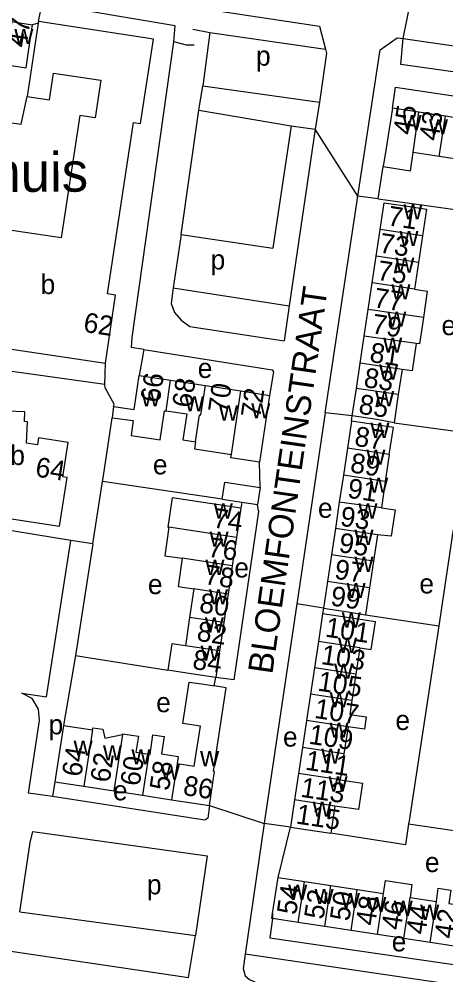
# Model space of a CAD drawing. Extents: x 163012 to 165277, y 382513 to 383987.
# Drawn here: x 163502.4 to 163589, y 383224 to 383417.8 of the extents above; entities that cross this region are included whole.
import ezdxf

# ---------------------------------------------------------------- set-up
doc = ezdxf.new("R2010")
doc.units = 0
for name, color, linetype in [('BLT_Basislijn', 7, 'Continuous'), ('BLT_Bebouwing', 7, 'Continuous'), ('BLT_Bebouwing_beschrifting', 7, 'Continuous'), ('BLT_Centroide', 7, 'Continuous'), ('BLT_Huisnummer', 7, 'Continuous'), ('BLT_Huisnummer_ tussenligend', 7, 'Continuous'), ('BLT_Onderverdeling_panden', 7, 'Continuous'), ('BLT_Straatnaam', 7, 'Continuous'), ('BLT_Vlakafsluiter', 7, 'Continuous')]:
    doc.layers.add(name, color=color, linetype=linetype)

msp = doc.modelspace()

# ---------------------------------------------------------------- linework, layer by layer
at = {"layer": 'BLT_Basislijn'}
for p, q in [((163506.38, 383417.32), (163507.11, 383420.98)), ((163506.33, 383417.01), (163505.14, 383416.66)), ((163537.69, 383415.82), (163541.14, 383415.15)), ((163541.14, 383415.15), (163539.72, 383404.32)), ((163580.33, 383413.88), (163605.73, 383410.21)), ((163538.92, 383399.38), (163539.72, 383404.32)), ((163539.72, 383404.32), (163563.35, 383400.97)), ((163535.3, 383374.17), (163538.92, 383399.38)), ((163538.92, 383399.38), (163557.66, 383396.21)), ((163563.35, 383400.97), (163562.49, 383395.52)), ((163557.66, 383396.21), (163553.89, 383371.35)), ((163557.66, 383396.21), (163562.49, 383395.52)), ((163575.3, 383381.36), (163576.31, 383387.91)), ((163564.55, 383337.96), (163571.19, 383381.89)), ((163575.3, 383381.36), (163571.19, 383381.89)), ((163533.7, 383363.31), (163557.22, 383359.7)), ((163527.73, 383350.8), (163526.81, 383345.53)), ((163519.82, 383343.69), (163485.89, 383348.51)), ((163519.82, 383343.69), (163519.94, 383348.06)), ((163570.03, 383337.36), (163564.55, 383337.96)), ((163569.85, 383336.26), (163570.03, 383337.36)), ((163578.51, 383335.96), (163593.55, 383333.89)), ((163551.34, 383322.82), (163551.22, 383328)), ((163517.38, 383311.39), (163519.36, 383324.07)), ((163543.64, 383320.43), (163519.36, 383324.07)), ((163547.62, 383319.84), (163547.43, 383318.62)), ((163550.99, 383318.07), (163551.02, 383317.97)), ((163512.92, 383312.11), (163497.29, 383314.66)), ((163590.52, 383314.29), (163587.56, 383294.8)), ((163508, 383280.37), (163512.92, 383312.11)), ((163517.38, 383311.39), (163512.92, 383312.11)), ((163517.38, 383311.39), (163513.9, 383288.76)), ((163564.18, 383298.34), (163558.8, 383299.24)), ((163564.18, 383298.34), (163564.02, 383297.21)), ((163572.72, 383297.03), (163587.56, 383294.8)), ((163513.9, 383288.76), (163511.42, 383274.58)), ((163513.9, 383288.76), (163532.64, 383285.77)), ((163542.02, 383282.58), (163542.32, 383284.32)), ((163502.99, 383281.11), (163508, 383280.37)), ((163509.68, 383263.14), (163509.22, 383260.12)), ((163509.22, 383260.12), (163504.38, 383260.8)), ((163557.47, 383253.93), (163552.15, 383254.66)), ((163554.99, 383243.74), (163557.47, 383253.93)), ((163581.46, 383254.63), (163597.96, 383252.2)), ((163502.59, 383236.74), (163538.23, 383231.93)), ((163553.88, 383236.45), (163553.82, 383235.38)), ((163463.3, 383234.3), (163536.83, 383223.46)), ((163536.83, 383223.46), (163538.23, 383231.93))]:
    msp.add_line(p, q, dxfattribs=at)
for points in [[(163389.35, 383444), (163390.61, 383444.5), (163392.76, 383444.65), (163405.07, 383441.7), (163432.57, 383436.22), (163489.01, 383427.6), (163533.29, 383420.96), (163563.38, 383416.41), (163564.62, 383411.74)], [(163533.82, 383413.21), (163534.13, 383416.47), (163507.11, 383420.98)], [(163541.14, 383415.15), (163564.62, 383411.74)], [(163527.73, 383350.8), (163525.21, 383351.24), (163525.36, 383353.23), (163533.82, 383413.21)], [(163537.98, 383412.53), (163536.41, 383412.53), (163533.82, 383413.21)], [(163571.19, 383381.89), (163575.68, 383411.58), (163579.12, 383414.03), (163580.33, 383413.88)], [(163605.73, 383410.21), (163604.9, 383405.14), (163579.87, 383408.64), (163580.33, 383413.88)], [(163564.62, 383411.74), (163564.81, 383410.91), (163563.35, 383400.97)], [(163578.16, 383399.8), (163578.81, 383404.02), (163627.18, 383396.81)], [(163483.5, 383399.29), (163502.86, 383396.53), (163504.09, 383402.15)], [(163562.49, 383395.52), (163557.22, 383359.7)], [(163575.3, 383381.36), (163585.09, 383380), (163600.04, 383377.94), (163599.84, 383373.27)], [(163535.3, 383374.17), (163533.7, 383363.31)], [(163535.3, 383374.17), (163553.89, 383371.35)], [(163533.7, 383363.31), (163533.27, 383360.13), (163533.95, 383358.32), (163535.29, 383356.79), (163537.09, 383355.49), (163556.19, 383352.61)], [(163557.22, 383359.7), (163556.19, 383352.61)], [(163527.73, 383350.8), (163553.77, 383346.71), (163554.08, 383346.29), (163553.26, 383341.52)], [(163521.58, 383339.27), (163521.71, 383339.74), (163519.91, 383343.02), (163519.82, 383343.69)], [(163564.55, 383337.96), (163558.86, 383299.64), (163558.8, 383299.24)], [(163519.36, 383324.07), (163519.54, 383325.21), (163521.29, 383336.99)], [(163551.02, 383317.97), (163546.03, 383283.81), (163542.32, 383284.32)], [(163550.99, 383318.07), (163550.82, 383319.37)], [(163558.8, 383299.24), (163552.24, 383255.24), (163552.15, 383254.66)], [(163587.56, 383294.8), (163581.55, 383255.2), (163581.46, 383254.63)], [(163504.38, 383260.8), (163506.6, 383275.54), (163506.36, 383277.84), (163505.1, 383280.02), (163502.99, 383281.11)], [(163541.05, 383258.31), (163540.72, 383255.76), (163540.14, 383255.38), (163509.22, 383260.12)], [(163552.15, 383254.66), (163548.32, 383228.18)], [(163581.46, 383254.63), (163580.8, 383250.37), (163565.65, 383252.71)], [(163502.59, 383236.74), (163504.67, 383250.85), (163505.24, 383253.04), (163540.6, 383248.13), (163538.23, 383231.93)], [(163553.82, 383235.38), (163553.31, 383231.45), (163601.31, 383224.5)], [(163548.32, 383228.18), (163547.89, 383225.23), (163548.33, 383223.8), (163549.18, 383223.01), (163550.64, 383222.36), (163551.73, 383222.16)], [(163600.65, 383220.44), (163548.32, 383228.18)]]:
    msp.add_lwpolyline(points, dxfattribs=at)
at = {"layer": 'BLT_Bebouwing'}
for p, q in [((163499.13, 383417.6), (163505.14, 383416.66)), ((163506.33, 383417.01), (163504.09, 383402.15)), ((163506.38, 383417.32), (163506.33, 383417.01)), ((163578.16, 383399.8), (163576.89, 383391.63)), ((163583.54, 383398.97), (163578.16, 383399.8)), ((163588.91, 383398.13), (163583.54, 383398.97)), ((163594.29, 383397.3), (163588.91, 383398.13)), ((163576.89, 383391.63), (163576.31, 383387.91)), ((163587.64, 383389.97), (163582.4, 383390.78)), ((163593.02, 383389.13), (163587.64, 383389.97)), ((163574.9, 383369.75), (163575.71, 383375.17)), ((163584.28, 383373.87), (163583.46, 383368.45)), ((163574.09, 383364.33), (163574.9, 383369.75)), ((163583.46, 383368.45), (163582.65, 383363.03)), ((163573.27, 383358.92), (163574.09, 383364.33)), ((163572.46, 383353.5), (163573.27, 383358.92)), ((163571.64, 383348.08), (163572.46, 383353.5)), ((163570.87, 383342.94), (163571.64, 383348.08)), ((163526.81, 383345.53), (163533.17, 383344.59)), ((163580.14, 383346.79), (163579.36, 383341.66)), ((163533.17, 383344.59), (163540.25, 383343.54)), ((163540.25, 383343.54), (163547.42, 383342.41)), ((163547.42, 383342.41), (163553.26, 383341.52)), ((163553.26, 383341.52), (163551.22, 383328)), ((163570.03, 383337.36), (163570.87, 383342.94)), ((163579.36, 383341.66), (163578.51, 383335.96)), ((163521.58, 383339.27), (163521.29, 383336.99)), ((163569.85, 383336.26), (163569.04, 383330.8)), ((163569.04, 383330.8), (163568.22, 383325.34)), ((163577.54, 383329.52), (163576.72, 383324.06)), ((163543.64, 383320.43), (163544.15, 383323.9)), ((163544.15, 383323.9), (163551.34, 383322.82)), ((163568.22, 383325.34), (163567.4, 383319.86)), ((163551.34, 383322.82), (163550.82, 383319.37)), ((163543.64, 383320.43), (163547.62, 383319.84)), ((163547.62, 383319.84), (163550.82, 383319.37)), ((163567.4, 383319.86), (163566.6, 383314.51)), ((163547.43, 383318.62), (163546.54, 383312.7)), ((163566.6, 383314.51), (163565.8, 383309.15)), ((163546.54, 383312.7), (163545.68, 383306.95)), ((163575.12, 383313.23), (163574.32, 383307.87)), ((163565.8, 383309.15), (163565, 383303.79)), ((163545.68, 383306.95), (163544.82, 383301.2)), ((163565, 383303.79), (163564.18, 383298.34)), ((163573.54, 383302.5), (163572.72, 383297.03)), ((163537.89, 383302.24), (163537.03, 383296.49)), ((163544.82, 383301.2), (163543.96, 383295.45)), ((163564.02, 383297.21), (163563.17, 383291.59)), ((163537.03, 383296.49), (163536.17, 383290.74)), ((163543.96, 383295.45), (163543.09, 383289.7)), ((163563.17, 383291.59), (163562.36, 383286.25)), ((163543.09, 383289.7), (163542.32, 383284.32)), ((163562.36, 383286.25), (163561.55, 383280.91)), ((163561.55, 383280.91), (163560.75, 383275.57)), ((163560.75, 383275.57), (163559.92, 383270.09)), ((163511.42, 383274.58), (163509.68, 383263.14)), ((163511.42, 383274.58), (163517.33, 383273.68)), ((163569.17, 383274.3), (163568.35, 383268.83)), ((163559.92, 383270.09), (163559.12, 383264.79)), ((163568.35, 383268.83), (163567.55, 383263.52)), ((163559.12, 383264.79), (163558.31, 383259.45)), ((163509.68, 383263.14), (163515.55, 383262.24)), ((163515.55, 383262.24), (163521.63, 383261.3)), ((163521.63, 383261.3), (163527.5, 383260.4)), ((163527.5, 383260.4), (163533.36, 383259.49)), ((163533.36, 383259.49), (163541.05, 383258.31)), ((163558.31, 383259.45), (163557.47, 383253.93)), ((163566.48, 383258.22), (163565.65, 383252.71)), ((163553.88, 383236.45), (163554.99, 383243.74)), ((163560.33, 383242.92), (163565.68, 383242.1)), ((163565.68, 383242.1), (163571.03, 383241.28)), ((163571.03, 383241.28), (163576.39, 383240.46)), ((163581.74, 383239.65), (163587.09, 383238.83)), ((163559.07, 383234.59), (163553.82, 383235.38)), ((163564.43, 383233.78), (163559.07, 383234.59)), ((163569.78, 383232.98), (163564.43, 383233.78)), ((163575.14, 383232.17), (163569.78, 383232.98)), ((163580.49, 383231.36), (163575.14, 383232.17)), ((163585.85, 383230.56), (163580.49, 383231.36)), ((163591.2, 383229.75), (163585.85, 383230.56))]:
    msp.add_line(p, q, dxfattribs=at)
for points in [[(163525.64, 383396.87), (163527.04, 383396.66), (163529.73, 383413.79), (163506.38, 383417.32)], [(163497.81, 383408.88), (163500, 383408.56), (163503.86, 383407.96), (163504.41, 383411.71), (163505.14, 383416.66)], [(163504.09, 383402.15), (163508.6, 383401.47), (163509.42, 383406.9), (163519.01, 383405.45), (163517.86, 383397.82)], [(163517.86, 383397.82), (163514.74, 383398.29), (163510.97, 383373.47)], [(163519.94, 383348.06), (163522.02, 383361.83), (163520.38, 383362.08), (163525.64, 383396.87)], [(163576.31, 383387.91), (163581.82, 383387.05), (163582.4, 383390.78)], [(163575.71, 383375.17), (163576.52, 383380.57), (163581.21, 383379.87), (163585.09, 383379.28), (163584.28, 383373.87)], [(163510.97, 383373.47), (163500, 383375.11), (163498.62, 383364.57), (163484.68, 383366.66), (163483.87, 383361.24), (163486.59, 383360.83)], [(163582.65, 383363.03), (163585.25, 383362.62), (163584.45, 383357.28)], [(163486.59, 383360.83), (163485.45, 383353.23), (163500, 383351.03), (163519.94, 383348.06)], [(163584.45, 383357.28), (163583.64, 383351.94), (163583, 383352.04)], [(163583, 383352.04), (163582.16, 383346.49), (163580.14, 383346.79)], [(163521.58, 383339.27), (163525.79, 383338.64), (163526.81, 383345.53)], [(163500, 383338.31), (163489.01, 383338.63), (163488.96, 383333.17), (163494.21, 383333.03), (163494, 383329.76), (163493.24, 383329.74), (163492.86, 383316.62), (163495.64, 383316.44), (163495.77, 383317.26), (163500, 383316.6), (163510.62, 383314.98), (163512.16, 383324.86), (163511.28, 383325), (163512.37, 383331.94), (163506.4, 383332.87), (163506.18, 383331.46), (163503.95, 383331.81), (163504.14, 383336.16), (163503.57, 383336.25), (163503.62, 383338.21), (163500, 383338.31)], [(163521.29, 383336.99), (163525.61, 383336.39), (163525.16, 383333.36), (163531.05, 383332.49), (163531.92, 383338.41), (163532.25, 383338.36)], [(163532.25, 383338.36), (163536.44, 383337.74), (163535.66, 383332.47), (163538.23, 383332.09)], [(163578.51, 383335.96), (163574.98, 383336.61), (163570.03, 383337.36)], [(163577.54, 383329.52), (163578.36, 383334.98), (163574.8, 383335.51), (163569.85, 383336.26)], [(163538.23, 383332.09), (163538.01, 383330.65), (163545.51, 383329.54)], [(163551.22, 383328), (163545.41, 383328.86), (163545.51, 383329.54)], [(163576.72, 383324.06), (163575.94, 383318.69)], [(163533.47, 383320.72), (163532.59, 383314.79), (163532.85, 383314.75)], [(163547.43, 383318.62), (163542.49, 383319.36), (163533.47, 383320.72)], [(163575.94, 383318.69), (163578.71, 383318.28), (163577.91, 383312.94), (163575.12, 383313.23)], [(163532.85, 383314.75), (163531.99, 383309), (163535.55, 383308.47)], [(163535.55, 383308.47), (163534.68, 383302.72), (163537.89, 383302.24)], [(163574.32, 383307.87), (163573.54, 383302.5)], [(163571.59, 383290.32), (163573.88, 383289.97), (163574.73, 383295.57), (163568.96, 383296.47), (163564.02, 383297.21)], [(163564.18, 383298.34), (163569.13, 383297.59), (163572.72, 383297.03)], [(163536.17, 383290.74), (163533.44, 383291.15), (163532.64, 383285.77)], [(163571.59, 383290.32), (163570.77, 383284.98)], [(163542.32, 383284.32), (163537.34, 383285.06), (163532.64, 383285.77)], [(163570.77, 383284.98), (163569.97, 383279.64)], [(163534.49, 383266.83), (163537.97, 383266.3), (163539.22, 383274.39), (163535.67, 383274.94), (163536.97, 383283.36), (163539.51, 383282.97), (163542.02, 383282.58)], [(163541.05, 383258.31), (163542.11, 383265.22), (163541.85, 383265.26), (163544.46, 383282.21), (163542.02, 383282.58)], [(163569.97, 383279.64), (163569.54, 383276.78), (163572.88, 383276.28), (163572.51, 383273.79), (163569.17, 383274.3)], [(163517.33, 383273.68), (163517.4, 383274.09), (163519.43, 383273.83), (163519.86, 383271.96), (163523.39, 383272.72)], [(163523.39, 383272.72), (163523.41, 383272.86)], [(163523.41, 383272.86), (163526.64, 383272.36), (163526.14, 383269.13), (163528.78, 383268.72)], [(163528.78, 383268.72), (163529.01, 383268.69), (163529.57, 383272.63), (163531.88, 383272.3), (163531.35, 383268.8), (163534.72, 383268.28), (163534.49, 383266.83)], [(163567.55, 383263.52), (163572.11, 383262.84), (163571.31, 383257.49), (163566.48, 383258.22)], [(163557.47, 383253.93), (163562.42, 383253.19), (163565.65, 383252.71)], [(163554.99, 383243.74), (163559.93, 383242.98), (163560.33, 383242.92)], [(163576.39, 383240.46), (163576.77, 383243.09), (163582.12, 383242.28), (163581.74, 383239.65)], [(163587.09, 383238.83), (163587.47, 383241.56), (163590.02, 383241.17), (163589.61, 383238.44), (163592.44, 383238.01)], [(163553.82, 383235.38), (163553.72, 383235.39), (163553.88, 383236.45)]]:
    msp.add_lwpolyline(points, dxfattribs=at)
at = {"layer": 'BLT_Onderverdeling_panden'}
for p, q in [((163582.4, 383390.78), (163583.54, 383398.97)), ((163587.64, 383389.97), (163588.91, 383398.13)), ((163584.28, 383373.87), (163575.71, 383375.17)), ((163583.46, 383368.45), (163574.9, 383369.75)), ((163582.65, 383363.03), (163574.09, 383364.33)), ((163584.45, 383357.28), (163573.27, 383358.92)), ((163583, 383352.04), (163572.46, 383353.5)), ((163580.14, 383346.79), (163571.64, 383348.08)), ((163532.25, 383338.36), (163533.17, 383344.59)), ((163545.51, 383329.54), (163547.42, 383342.41)), ((163579.36, 383341.66), (163570.87, 383342.94)), ((163577.54, 383329.52), (163569.04, 383330.8)), ((163576.72, 383324.06), (163568.22, 383325.34)), ((163575.94, 383318.69), (163567.4, 383319.86)), ((163546.54, 383312.7), (163532.85, 383314.75)), ((163575.12, 383313.23), (163566.6, 383314.51)), ((163545.68, 383306.95), (163535.55, 383308.47)), ((163574.32, 383307.87), (163565.8, 383309.15)), ((163573.54, 383302.5), (163565, 383303.79)), ((163544.82, 383301.2), (163537.89, 383302.24)), ((163543.96, 383295.45), (163537.03, 383296.49)), ((163543.09, 383289.7), (163536.17, 383290.74)), ((163571.59, 383290.32), (163563.17, 383291.59)), ((163570.77, 383284.98), (163562.36, 383286.25)), ((163569.97, 383279.64), (163561.55, 383280.91)), ((163569.17, 383274.3), (163560.75, 383275.57)), ((163517.33, 383273.68), (163515.55, 383262.24)), ((163523.39, 383272.72), (163521.63, 383261.3)), ((163568.35, 383268.83), (163559.92, 383270.09)), ((163528.78, 383268.72), (163527.5, 383260.4)), ((163534.49, 383266.83), (163533.36, 383259.49)), ((163567.55, 383263.52), (163559.12, 383264.79)), ((163566.48, 383258.22), (163558.31, 383259.45)), ((163559.07, 383234.59), (163560.33, 383242.92)), ((163564.43, 383233.78), (163565.68, 383242.1)), ((163569.78, 383232.98), (163571.03, 383241.28)), ((163575.14, 383232.17), (163576.39, 383240.46)), ((163580.49, 383231.36), (163581.74, 383239.65)), ((163585.85, 383230.56), (163587.09, 383238.83))]:
    msp.add_line(p, q, dxfattribs=at)
msp.add_lwpolyline([(163538.23, 383332.09), (163539.04, 383337.58), (163539.31, 383337.54), (163540.25, 383343.54)], dxfattribs=at)
at = {"layer": 'BLT_Vlakafsluiter'}
for p, q in [((163580.33, 383413.88), (163582.6, 383425.12)), ((163571.19, 383381.89), (163562.49, 383395.52)), ((163541.05, 383258.31), (163552.15, 383254.66))]:
    msp.add_line(p, q, dxfattribs=at)

# ---------------------------------------------------------------- texts
at = {"layer": 'BLT_Bebouwing_beschrifting'}
msp.add_text('Gemeenschapshuis', height=8, rotation=0.2051, dxfattribs=at).set_placement((163421.9, 383382.51))
at = {"layer": 'BLT_Centroide'}
for s, p in [('w', (163501.47, 383412.78)), ('p', (163550.5, 383408.39)), ('w', (163580.22, 383395.3)), ('w', (163585.59, 383394.47)), ('w', (163580.4, 383377.22)), ('w', (163579.59, 383371.81)), ('p', (163541.29, 383367.05)), ('w', (163578.77, 383366.41)), ('b', (163506.8, 383362.06)), ('w', (163577.96, 383360.97)), ('w', (163577.12, 383355.44)), ('e', (163588.13, 383353.73)), ('w', (163576.3, 383350.16)), ('e', (163538.68, 383345.05)), ('w', (163575.48, 383344.72)), ('w', (163527.23, 383339.27)), ('w', (163536.09, 383338.28)), ('w', (163574.67, 383339.31)), ('w', (163543, 383336.41)), ('w', (163549.53, 383336.86)), ('w', (163573.7, 383332.88)), ('b', (163500.66, 383327.39)), ('w', (163572.88, 383327.44)), ('e', (163529.58, 383325.49)), ('w', (163573.46, 383321.75)), ('w', (163541.93, 383316.53)), ('e', (163563.07, 383316.68)), ('w', (163571.27, 383316.53)), ('w', (163570.46, 383311.19)), ('w', (163541.08, 383310.81)), ('w', (163570.47, 383305.72)), ('w', (163540.23, 383305.09)), ('e', (163546.1, 383304.57)), ('e', (163528.57, 383301.2)), ('e', (163583.64, 383301.33)), ('w', (163568.86, 383300.41)), ('w', (163540.96, 383299.12)), ('w', (163567.9, 383294.41)), ('w', (163540.11, 383293.41)), ('w', (163539.26, 383287.69)), ('w', (163567.13, 383289.28)), ('w', (163566.33, 383284.03)), ('w', (163565.45, 383278.22)), ('e', (163530.25, 383277.25)), ('p', (163508.42, 383272.75)), ('e', (163578.78, 383273.64)), ('e', (163555.97, 383270.27)), ('w', (163565.41, 383272.06)), ('w', (163513.5, 383268.41)), ('w', (163519.45, 383267.48)), ('w', (163525.22, 383266.67)), ('w', (163563.73, 383266.81)), ('w', (163539.16, 383266.28)), ('w', (163531.19, 383263.59)), ('w', (163565.21, 383261.16)), ('e', (163521.49, 383259.37)), ('w', (163561.98, 383256.06)), ('e', (163584.77, 383244.82)), ('p', (163528.37, 383240.3)), ('w', (163557.02, 383239.17)), ('w', (163562.38, 383238.34)), ('w', (163567.73, 383237.53)), ('w', (163573.08, 383236.72)), ('w', (163578.44, 383235.92)), ('w', (163583.8, 383235.11)), ('e', (163578.03, 383228.73))]:
    msp.add_text(s, height=4, dxfattribs=at).set_placement(p)
at = {"layer": 'BLT_Huisnummer'}
for s, rotation, p in [('47', 81.4779, (163503.91, 383411.92)), ('45', 81.1737, (163582.21, 383394.19)), ('71', 351.3596, (163577.04, 383376.03)), ('75', 351.3571, (163574.92, 383364.98)), ('62', 351.5183, (163515.33, 383354.42)), ('79', 351.3579, (163573.82, 383354.14)), ('83', 351.3596, (163572.21, 383343.23)), ('66', 81.5674, (163530.96, 383339.89)), ('72', 81.5631, (163551.35, 383336.79)), ('87', 351.3638, (163570.32, 383331.33)), ('64', 351.1213, (163505.57, 383325.09)), ('91', 351.4551, (163568.91, 383320.78)), ('74', 351.4709, (163541.62, 383314.74)), ('95', 351.458, (163567.14, 383309.75)), ('78', 351.4684, (163539.89, 383303.27)), ('99', 351.4561, (163565.48, 383298.93)), ('103', 351.4602, (163563.55, 383287.04)), ('84', 351.476, (163537.45, 383286.06)), ('107', 351.446, (163562.2, 383276.11)), ('64', 81.2653, (163515.04, 383264.01)), ('111', 351.452, (163560.35, 383265.61)), ('58', 81.2426, (163532.82, 383261.18)), ('86', 351.2473, (163535.55, 383260.49)), ('115', 351.4551, (163558.46, 383254.69)), ('54', 81.4403, (163558.64, 383236.01)), ('50', 81.4388, (163569.4, 383234.73)), ('46', 81.4391, (163579.85, 383232.92)), ('42', 81.4387, (163590.59, 383231.15))]:
    msp.add_text(s, height=4, rotation=rotation, dxfattribs=at).set_placement(p)
at = {"layer": 'BLT_Huisnummer_ tussenligend'}
for s, rotation, p in [('43', 81.1726, (163587.49, 383392.98)), ('73', 351.3596, (163575.37, 383370.53)), ('77', 351.3571, (163574.21, 383359.42)), ('81', 351.3579, (163573.4, 383348.33)), ('68', 81.5674, (163537.4, 383338.86)), ('70', 81.5674, (163544.7, 383337.8)), ('85', 351.3596, (163571.17, 383337.84)), ('89', 351.3638, (163569.46, 383325.93)), ('93', 351.4551, (163567.42, 383315.1)), ('76', 351.4709, (163540.58, 383308.83)), ('97', 351.458, (163566.26, 383304.36)), ('80', 351.4684, (163538.84, 383297.53)), ('82', 351.4684, (163538.33, 383291.78)), ('101', 351.4561, (163564.39, 383292.6)), ('105', 351.4602, (163562.87, 383281.65)), ('109', 351.446, (163561.06, 383270.88)), ('62', 81.2392, (163520.79, 383262.83)), ('60', 81.2392, (163526.87, 383262.12)), ('113', 351.452, (163559.38, 383260.11)), ('52', 81.4388, (163564.18, 383235.09)), ('48', 81.4391, (163574.63, 383233.8)), ('44', 81.4387, (163584.85, 383232))]:
    msp.add_text(s, height=4, rotation=rotation, dxfattribs=at).set_placement(p)
at = {"layer": 'BLT_Straatnaam'}
msp.add_text('BLOEMFONTEINSTRAAT', height=5, rotation=81.826, dxfattribs=at).set_placement((163553.8, 383284.82))

doc.saveas('drawing.dxf')
